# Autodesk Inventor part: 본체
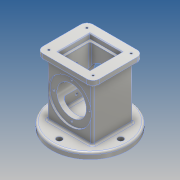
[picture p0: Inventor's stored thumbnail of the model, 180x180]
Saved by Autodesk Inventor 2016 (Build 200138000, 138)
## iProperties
Created: 2018-10
Part Number: 본체
Material: 알루미늄 6061
Document SubType Name: Modeling
Designer: Administrator
Density: 2.7 g/cm^3
Appearance: 알루미늄 - 평지
Mass: 984.574 g
Surface Area: 743.905 cm^2
Volume: 364.657 cm^3
Author: Administrator
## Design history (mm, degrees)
sketch "스케치1"
  geometry: L1 (-37, 33)-(37, 33); L2 (37, 33)-(37, -33); L3 (37, -33)-(-37, -33); L4 (-37, -33)-(-37, 33); L5 (-37, 33)-(37, -33); L6 (37, 33)-(-37, -33); 1 further point
  constraints: 12 end point, 2 midpoint, 2 parallel, 1 horizontal, 1 perpendicular
  dimensions: "d0" = 74 distance of L1.start L1.end; "d1" = 66 distance of L3.end L1.start
extrude "돌출1" new body sketch "스케치1" distance "d2" = 88; taper "d3" = 0 deg
sketch "스케치2"
  geometry: L1 (37, 33)-(-37, 33) reference; L2 (-37, 33)-(-37, -33) reference; L3 (-37, -33)-(37, -33) reference; L4 (37, -33)-(37, 33) reference; L5 (-46, 41)-(46, 41); L6 (46, 41)-(46, -41); L7 (46, -41)-(-46, -41); L8 (-46, -41)-(-46, 41); L9 (-46, 41)-(46, -41); L10 (46, 41)-(-46, -41); 1 further point
  constraints: 12 end point, 2 midpoint, 2 parallel, 1 horizontal, 1 perpendicular
  dimensions: "d4" = 92 distance of L5.start L5.end; "d5" = 82 distance of L5.end L6.end
extrude "돌출2" join sketch "스케치2" distance "d6" = 10; taper "d7" = 0 deg
sketch "스케치3"
  geometry: L1 (37, 33)-(-37, 33) reference; L2 (-37, 33)-(-37, -33) reference; L3 (-37, -33)-(37, -33) reference; L4 (37, -33)-(37, 33) reference; C1 r 62.5 at (0, 0); 1 further point
  constraints: 1 centre point, 1 coincident
  dimensions: "d8" = 125 diameter of C1
extrude "돌출3" join sketch "스케치3" distance "d9" = 10; taper "d10" = 0 deg
sketch "스케치5"
  geometry: L1 (-46, 98)-(46, 98) reference; L2 (-62.5, -10)-(62.5, -10) reference; L3 (0, -10)-(0, 8); L4 (0, 8)-(-24.826, 8); L5 (-24.826, 8)-(-28, -10); L6 (0, -10)-(-28, -10); L7 (62.5, -10)-(-62.5, -10); L8 (0, 8)-(24.826, 8); L9 (24.826, 8)-(28, -10); L10 (0, -10)-(28, -10); 1 further point
  constraints: 16 end point, 4 symmetric about line, 2 point on line, 1 collinear, 1 midpoint, 1 perpendicular, 1 vertical
  dimensions: "d11" = 18 distance of L3.start L3.end; "d12" = 56 distance of L5.end L9.end; "d13" = 80 deg angle of L2 L9
revolve "회전1" sketch "스케치5" stored, may be unused: angle "d14" = 90 deg
fillet "모깎기1" dims "d15" = 3
sketch "스케치6"
  geometry: L1 (46, 41)-(-46, 41) reference; L2 (-46, 41)-(-46, -41) reference; L3 (-46, -41)-(46, -41) reference; L4 (46, -41)-(46, 41) reference; L5 (-26, 26)-(26, 26); L6 (26, 26)-(26, -26); L7 (26, -26)-(-26, -26); L8 (-26, -26)-(-26, 26); L9 (-26, 26)-(26, -26); L10 (26, 26)-(-26, -26); 1 further point
  constraints: 12 end point, 2 midpoint, 2 parallel, 1 horizontal, 1 perpendicular
  dimensions: "d17" = 52 distance of L5.start L5.end; "d18" = 52 distance of L7.end L5.start
extrude "돌출4" cut sketch "스케치6" distance "d19" = 8; taper "d20" = 0 deg
sketch "스케치8"
  geometry: L1 (74, -88)-(74, 0) reference; L2 (0, 0)-(74, 0) reference; L3 (0, -88)-(0, 0) reference; L4 (-25.5, -98)-(99.5, -98) reference; L5 (65, -98)-(9, -98) reference; L6 (37, -98)-(37, -44); L7 (74, -88)-(0, -88) reference; C1 r 35 at (37, -44); 1 further point
  constraints: 2 end point, 1 centre point, 1 coincident, 1 midpoint, 1 vertical
  dimensions: "d21" = 54 distance of L6.start L6.end; "d22" = 70 diameter of C1
extrude "돌출5" cut sketch "스케치8" distance "d23" = 3; taper "d24" = 0 deg
sketch "스케치9"
  geometry: C1 r 35 at (0, 0) reference; C2 r 24 at (0, 0); 1 further point
  constraints: 1 centre point, 1 coincident
  dimensions: "d25" = 48 diameter of C2
extrude "돌출6" cut sketch "스케치9" stored distance "d26" = 0; taper "d27" = 0 deg
sketch "스케치10"
  geometry: L1 (-26, 26)-(26, 26) reference; L2 (-26, -26)-(-26, 26) reference; L3 (26, -26)-(-26, -26) reference; L4 (26, 26)-(26, -26) reference; L5 (-19, 22)-(19, 22); L6 (22, 19)-(22, -19); L7 (19, -22)-(-19, -22); L8 (-22, -19)-(-22, 19); L9 (-22, 22)-(22, -22); L10 (22, 22)-(-22, -22); A1 r 3 centre (19, -19) between (19, -22) and (22, -19); A2 r 3 centre (19, 19) between (22, 19) and (19, 22); A3 r 3 centre (-19, 19) between (-19, 22) and (-22, 19); A4 r 3 centre (-19, -19) between (-22, -19) and (-19, -22); 1 further point
  constraints: 12 end point, 8 point on circle, 8 point on line, 8 tangent, 4 centre point, 3 equal radius, 2 midpoint, 2 parallel, 1 horizontal, 1 perpendicular
  dimensions: "d28" = 44 distance of L9.start L10.start; "d29" = 44 distance of L10.end L9.start; "d36" = 3 radius of A1
extrude "돌출7" cut sketch "스케치10" distance "d30" = 74; taper "d31" = 0 deg
fillet "모깎기3" dims "d32" = 10
fillet "모깎기4" dims "d33" = 3
fillet "모깎기5" dims "d34" = 3
fillet "모깎기6" dims "d35" = 3
chamfer "모따기1" distance "d37" = 1; stored, may be unused: second distance "d38" = 2, angle "d39" = 45 deg
sketch "스케치11"
  geometry: L1 (36, 41)-(-36, 41) reference; L2 (-46, 31)-(-46, -31) reference; L3 (-36, -41)-(36, -41) reference; L4 (46, -31)-(46, 31) reference; L5 (-27, 27)-(-27, -27) reference; L6 (27, 27)-(-27, 27) reference; L7 (27, -27)-(27, 27) reference; L8 (-27, -27)-(27, -27) reference; A1 r 10 centre (36, 31) between (46, 31) and (36, 41) reference; A2 r 10 centre (-36, 31) between (-36, 41) and (-46, 31) reference; A3 r 10 centre (-36, -31) between (-46, -31) and (-36, -41) reference; A4 r 10 centre (36, -31) between (36, -41) and (46, -31) reference; 5 further points
  constraints: 4 coincident
hole "구멍1" sketch "스케치11" at (-36, -31), (-36, 31), (36, 31), (36, -31) diameter "d40" = 3.242; stored, may be unused: countersink angle "d44" = 90 deg, drill point angle "d46" = 118 deg; dims "d41" = 4, "d42" = 4, "d43" = 2, "d45" = 6
sketch "스케치12" dims "d47" = 58
  geometry: L1 (0, 0)-(0, 29); C1 r 24 at (0, 0) reference; C2 r 35 at (0, 0) reference; 2 further points
  constraints: 2 coincident, 2 end point, 1 vertical, 1 vertical alignment, 2 other
hole "구멍2" sketch "스케치12" at (0, 29) diameter "d48" = 3.242; stored, may be unused: countersink angle "d52" = 90 deg, drill point angle "d54" = 118 deg; dims "d49" = 4, "d50" = 4, "d51" = 2, "d53" = 6
sketch "스케치13" dims "d58" = 100
  geometry: L1 (40, -30)-(40, 30) reference; L2 (-34, -36)-(34, -36) reference; L3 (-40, 30)-(-40, -30) reference; L4 (34, 36)-(-34, 36) reference; L5 (0, 0)-(0, -50); C1 r 59.5 at (0, 0) reference; C2 r 4.5 at (0, -50); A1 r 6 centre (34, 30) between (40, 30) and (34, 36) reference; A2 r 6 centre (34, -30) between (34, -36) and (40, -30) reference; A3 r 6 centre (-34, -30) between (-40, -30) and (-34, -36) reference; A4 r 6 centre (-34, 30) between (-34, 36) and (-40, 30) reference; 1 further point
  constraints: 2 coincident, 2 end point, 1 centre point, 1 vertical, 1 vertical alignment, 2 other
  dimensions: "d60" = 9 diameter of C2
extrude "돌출8" cut sketch "스케치13" stored distance "d61" = 74; taper "d62" = 0 deg
node "작업 평면1"
sketch "스케치15"
  geometry: L1 (72, 0)-(0, 0) reference; L2 (82, 0)-(72, 0) reference; L3 (82, 0)-(36, 0); L4 (36, 0)-(36, 4); 2 further points
  constraints: 4 end point, 1 coincident, 1 midpoint, 1 perpendicular, 1 other
  dimensions: "d76" = 46 distance of L2.start L3.end; "d77" = 4 distance of L3.end L4.end
feature "엠보싱1" sketch "스케치15" dims "d0" = 74, "d1" = 66, "d78" = 0.5, "d79" = 0
sketch "스케치16"
  geometry: L1 (82, 60)-(82, 0) reference; L2 (0, 60)-(82, 60) reference; L3 (0, 0)-(0, 60) reference; L4 (82, 0)-(0, 0) reference; L5 (-13, 92.5)-(-13, -32.5) reference; L6 (-13, 2)-(-13, 58) reference; L7 (-13, 30)-(24, 30); L8 (24, 30)-(67, 30); 3 further points
  constraints: 4 end point, 2 coincident, 1 horizontal, 1 midpoint, 1 point on line
  dimensions: "d80" = 37 distance of L7.start L7.end; "d81" = 43 distance of L7.end L8.end
hole "구멍4" sketch "스케치16" at (67, 30), (24, 30) diameter "d82" = 4.134; stored, may be unused: countersink angle "d86" = 90 deg, drill point angle "d88" = 118 deg; dims "d83" = 50, "d84" = 4, "d85" = 2, "d87" = 50
fillet "모깎기7" dims "d89" = 3
node "솔리드1"
mirror "대칭1"
pattern_circular "원형 패턴1" dims angle "d56" = 360 deg
mirror "대칭2"
pattern_circular "원형 패턴2" dims angle "d64" = 360 deg
node "투영된 루프1"
node "투영된 루프2"
node "투영된 루프3"
node "투영된 루프4"
node "투영된 루프5"
node "투영된 루프6"
node "투영된 루프7"
node "투영된 루프8"
node "투영된 루프9"
node "투영된 루프11"
other parameters: "d75" = 88, "d90" = 0.5, "d91" = 2, "d92" = 37
